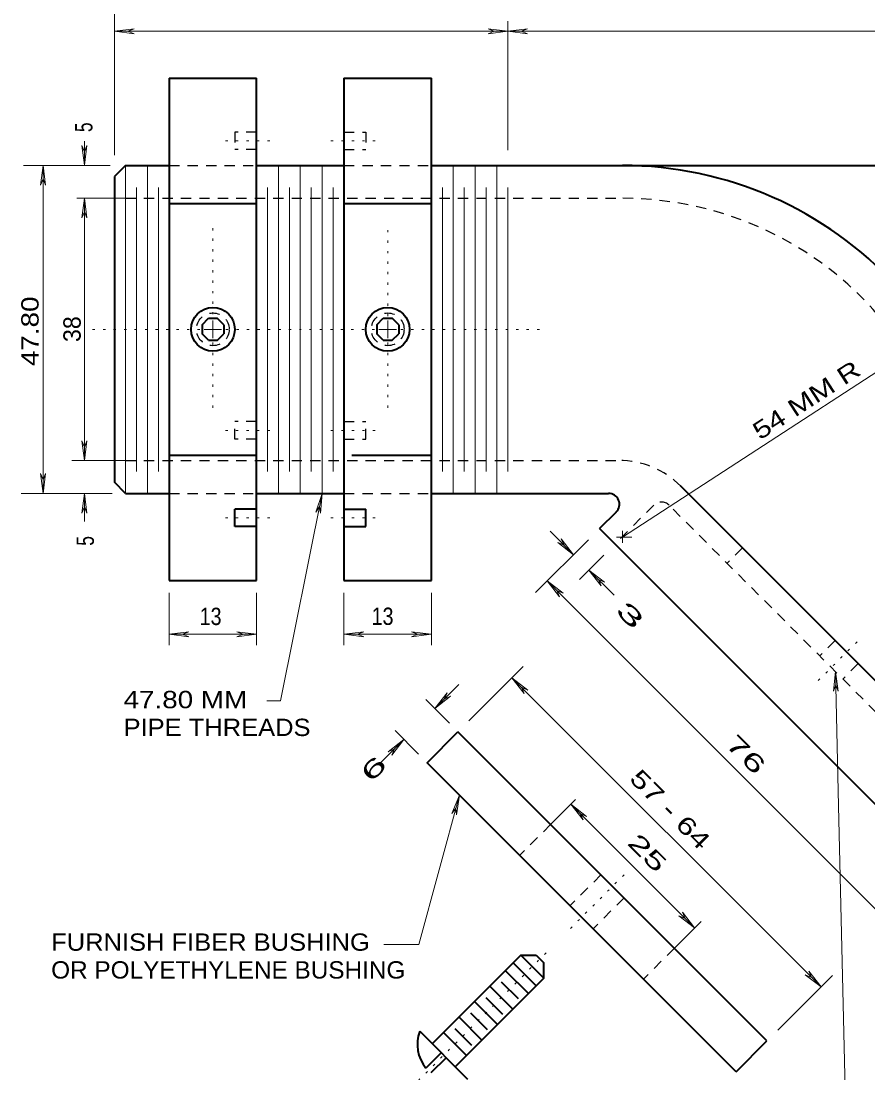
# Model space of a CAD drawing. Extents: x 312583 to 312854, y 144419 to 144597.
# Drawn here: x 312617.84 to 312654.99, y 144442.87 to 144489 of the extents above; entities that cross this region are included whole.
import ezdxf

# ---------------------------------------------------------------- set-up
doc = ezdxf.new("R2010")
doc.units = 0
doc.header["$LTSCALE"] = 0.3
doc.linetypes.add('DOTTED', pattern=[1.5, 0.3, -1.2])
doc.linetypes.add('SHORT_DASHED', pattern=[2.7, 1.5, -1.2])
doc.layers.add('1', color=7, linetype='Continuous', lineweight=40)
doc.layers.add('2', color=7, linetype='Continuous', lineweight=13)

msp = doc.modelspace()

# ---------------------------------------------------------------- linework, layer by layer
at = {"layer": '1'}
for p, q in [((312624.3434, 144486.4942), (312628.1767, 144486.4942)), ((312624.3434, 144486.4942), (312624.3434, 144464.4602)), ((312628.1767, 144464.4602), (312628.1767, 144486.4942)), ((312632.01, 144486.4942), (312635.8434, 144486.4942)), ((312632.01, 144486.4942), (312632.01, 144464.4602)), ((312635.8434, 144464.4602), (312635.8434, 144486.4942)), ((312622.4267, 144482.6609), (312621.9437, 144482.1779)), ((312622.4267, 144482.6609), (312624.3434, 144482.6609)), ((312628.1767, 144482.6609), (312632.01, 144482.6609)), ((312635.8434, 144482.6609), (312667.9437, 144482.6609)), ((312621.9437, 144482.1779), (312621.9437, 144468.7689)), ((312624.3434, 144480.9896), (312628.1767, 144480.9896)), ((312632.01, 144480.9896), (312635.8434, 144480.9896)), ((312625.7847, 144475.6766), (312626.0684, 144475.9602)), ((312626.0684, 144475.9602), (312626.4517, 144475.9602)), ((312626.743, 144475.6689), (312626.4517, 144475.9602)), ((312633.4514, 144475.6766), (312633.735, 144475.9602)), ((312633.735, 144475.9602), (312634.1184, 144475.9602)), ((312634.4097, 144475.6689), (312634.1184, 144475.9602)), ((312625.7847, 144475.6766), (312625.7847, 144475.2779)), ((312626.4594, 144475.0019), (312626.743, 144475.2856)), ((312626.743, 144475.6689), (312626.743, 144475.2856)), ((312633.4514, 144475.6766), (312633.4514, 144475.2779)), ((312634.126, 144475.0019), (312634.4097, 144475.2856)), ((312634.4097, 144475.6689), (312634.4097, 144475.2856)), ((312626.0607, 144475.0019), (312625.7847, 144475.2779)), ((312626.0607, 144475.0019), (312626.4594, 144475.0019)), ((312633.7274, 144475.0019), (312633.4514, 144475.2779)), ((312633.7274, 144475.0019), (312634.126, 144475.0019)), ((312624.3434, 144469.9649), (312628.1767, 144469.9649)), ((312632.355, 144469.9649), (312635.8434, 144469.9649)), ((312622.4267, 144468.2859), (312621.9437, 144468.7689)), ((312662.1937, 144453.1902), (312646.776, 144468.6079)), ((312622.4267, 144468.2859), (312624.3434, 144468.2859)), ((312628.1767, 144468.2859), (312632.01, 144468.2859)), ((312635.8434, 144468.2859), (312643.6097, 144468.2859)), ((312628.1767, 144467.5959), (312627.2184, 144467.5959)), ((312627.2184, 144466.8292), (312627.2184, 144467.5959)), ((312632.01, 144467.5959), (312632.9684, 144467.5959)), ((312632.9684, 144466.8292), (312632.9684, 144467.5959)), ((312643.947, 144467.4656), (312643.2187, 144466.7372)), ((312628.1767, 144466.8292), (312627.2184, 144466.8292)), ((312632.01, 144466.8292), (312632.9684, 144466.8292)), ((312659.4797, 144450.4762), (312643.2187, 144466.7372)), ((312624.3434, 144464.4602), (312628.1767, 144464.4602)), ((312632.01, 144464.4602), (312635.8434, 144464.4602)), ((312650.5634, 144444.2739), (312637.0087, 144457.8286)), ((312639.761, 144448.0382), (312635.874, 144444.1512)), ((312639.4237, 144447.7009), (312640.4357, 144446.6889)), ((312639.761, 144448.0382), (312640.4357, 144448.0382)), ((312640.4357, 144448.0382), (312640.773, 144447.7009)), ((312639.0864, 144447.3636), (312640.0984, 144446.3516)), ((312639.5847, 144447.5399), (312640.3207, 144446.8039)), ((312640.773, 144447.0262), (312636.886, 144443.1392)), ((312638.91, 144446.8652), (312639.646, 144446.1292)), ((312638.404, 144446.6812), (312639.416, 144445.6692)), ((312637.7294, 144446.0066), (312638.7414, 144444.9946)), ((312638.2277, 144446.1829), (312638.9637, 144445.4469)), ((312637.047, 144445.3242), (312638.059, 144444.3122)), ((312637.553, 144445.5082), (312638.289, 144444.7722)), ((312635.3297, 144444.6956), (312637.4304, 144442.5949)), ((312636.3724, 144444.6496), (312637.3844, 144443.6376)), ((312636.8707, 144444.8259), (312637.6067, 144444.0899)), ((312649.2064, 144442.9169), (312650.5634, 144444.2739)), ((312636.2727, 144443.7526), (312635.6057, 144443.0856)), ((312636.4874, 144443.5379), (312635.8204, 144442.8709))]:
    msp.add_line(p, q, dxfattribs=at)
at = {"layer": '1', "linetype": 'SHORT_DASHED', "lineweight": 25}
for p, q in [((312627.2184, 144484.1252), (312627.2184, 144483.3586)), ((312628.1767, 144484.1252), (312627.2184, 144484.1252)), ((312632.01, 144484.1252), (312632.9684, 144484.1252)), ((312632.9684, 144484.1252), (312632.9684, 144483.3586)), ((312628.1767, 144483.3586), (312627.2184, 144483.3586)), ((312632.01, 144483.3586), (312632.9684, 144483.3586)), ((312624.3434, 144482.6609), (312628.1767, 144482.6609)), ((312632.01, 144482.6609), (312635.8434, 144482.6609)), ((312622.4267, 144481.2272), (312644.223, 144481.2272)), ((312628.1767, 144471.4292), (312627.2184, 144471.4292)), ((312627.2184, 144470.6626), (312627.2184, 144471.4292)), ((312632.01, 144471.4292), (312632.9684, 144471.4292)), ((312632.9684, 144470.6626), (312632.9684, 144471.4292)), ((312628.1767, 144470.6626), (312627.2184, 144470.6626)), ((312632.01, 144470.6626), (312632.9684, 144470.6626)), ((312622.4267, 144469.7272), (312644.0697, 144469.7272)), ((312624.3434, 144468.2859), (312628.1767, 144468.2859)), ((312632.01, 144468.2859), (312635.8434, 144468.2859)), ((312645.5954, 144467.7646), (312643.8934, 144466.0626)), ((312660.507, 144453.5276), (312646.27, 144467.7646)), ((312649.49, 144465.8939), (312648.8154, 144465.2192)), ((312653.5534, 144461.8306), (312652.8787, 144461.1559)), ((312654.5654, 144460.8186), (312653.8907, 144460.1439)), ((312641.072, 144453.7652), (312639.715, 144452.4082)), ((312643.28, 144451.5572), (312641.923, 144450.2002)), ((312644.292, 144450.5452), (312642.935, 144449.1882)), ((312646.5, 144448.3372), (312645.143, 144446.9802))]:
    msp.add_line(p, q, dxfattribs=at)
at = {"layer": '1', "linetype": 'DOTTED', "lineweight": 13}
for p, q in [((312628.7517, 144483.7419), (312626.6357, 144483.7419)), ((312631.435, 144483.7419), (312633.551, 144483.7419)), ((312628.7517, 144471.0459), (312626.6357, 144471.0459)), ((312631.435, 144471.0459), (312633.551, 144471.0459)), ((312628.7517, 144467.2126), (312626.6357, 144467.2126)), ((312631.435, 144467.2126), (312633.551, 144467.2126)), ((312654.5117, 144461.7769), (312652.779, 144460.0442)), ((312644.292, 144451.5572), (312641.923, 144449.1882)), ((312640.8727, 144448.1379), (312635.1994, 144442.4646))]:
    msp.add_line(p, q, dxfattribs=at)
at = {"layer": '1', "lineweight": 13}
for p, q in [((312622.4267, 144482.6609), (312622.4267, 144468.2859)), ((312623.385, 144482.6609), (312623.385, 144468.2859)), ((312629.135, 144482.6609), (312629.135, 144468.2859)), ((312630.0934, 144482.6609), (312630.0934, 144468.2859)), ((312631.0517, 144482.6609), (312631.0517, 144468.2859)), ((312636.8017, 144482.6609), (312636.8017, 144468.2859)), ((312637.76, 144482.6609), (312637.76, 144468.2859)), ((312638.7184, 144482.6609), (312638.7184, 144468.2859)), ((312622.9097, 144481.7026), (312622.9097, 144469.2442)), ((312623.868, 144481.7026), (312623.868, 144469.2442)), ((312628.6597, 144481.7026), (312628.6597, 144469.2442)), ((312629.618, 144481.7026), (312629.618, 144469.2442)), ((312630.5764, 144481.7026), (312630.5764, 144469.2442)), ((312631.5347, 144481.7026), (312631.5347, 144469.2442)), ((312636.3264, 144481.7026), (312636.3264, 144469.2442)), ((312637.2847, 144481.7026), (312637.2847, 144469.2442)), ((312638.243, 144481.7026), (312638.243, 144469.2442)), ((312639.1937, 144481.7026), (312639.1937, 144469.2442))]:
    msp.add_line(p, q, dxfattribs=at)
at = {"layer": '1'}
for points in [[(312649.2064, 144442.9169), (312635.6517, 144456.4716), (312637.0087, 144457.8286)], [(312639.761, 144448.0382), (312640.773, 144447.0262), (312640.773, 144447.7009)]]:
    msp.add_lwpolyline(points, dxfattribs=at)
for centre in [(312626.26, 144475.4772), (312633.9267, 144475.4772)]:
    msp.add_circle(centre, 0.9583, dxfattribs=at)
at = {"layer": '1', "linetype": 'SHORT_DASHED', "lineweight": 25}
for centre in [(312626.26, 144475.4772), (312633.9267, 144475.4772)]:
    msp.add_circle(centre, 0.7188, dxfattribs=at)
at = {"layer": '1'}
for centre, radius, start, end in [((312644.223, 144466.3692), 16.2917, 354.95144, 90), ((312643.6106, 144467.8067), 0.4792, 315, 90), ((312636.8603, 144444.1255), 1.6333, 159.57183, 219.65516)]:
    msp.add_arc(centre, radius, start, end, dxfattribs=at)
at = {"layer": '1', "linetype": 'SHORT_DASHED', "lineweight": 25}
for centre, radius, start, end in [((312644.223, 144466.3692), 14.8542, 354.46141, 90), ((312644.0689, 144465.8939), 3.8333, 45, 90), ((312645.9327, 144467.4243), 0.4792, 45, 135)]:
    msp.add_arc(centre, radius, start, end, dxfattribs=at)
at = {"layer": '2'}
for p, q in [((312621.9437, 144483.1132), (312621.9437, 144491.9452)), ((312639.1937, 144483.3356), (312639.1937, 144488.9859)), ((312621.9437, 144488.5489), (312622.81, 144488.6562)), ((312621.9437, 144488.5489), (312622.81, 144488.4416)), ((312622.81, 144488.6562), (312622.534, 144488.5489)), ((312622.81, 144488.4416), (312622.534, 144488.5489)), ((312638.3274, 144488.6562), (312638.6034, 144488.5489)), ((312639.1937, 144488.5489), (312638.3274, 144488.6562)), ((312638.3274, 144488.4416), (312638.6034, 144488.5489)), ((312639.1937, 144488.5489), (312638.3274, 144488.4416)), ((312639.1937, 144488.5489), (312640.06, 144488.6562)), ((312639.1937, 144488.5489), (312640.06, 144488.4416)), ((312640.06, 144488.6562), (312639.784, 144488.5489)), ((312640.06, 144488.4416), (312639.784, 144488.5489)), ((312620.6222, 144482.6762), (312620.6222, 144483.7342)), ((312620.5149, 144483.5426), (312620.6222, 144483.2666)), ((312620.6222, 144482.6762), (312620.5149, 144483.5426)), ((312620.7295, 144483.5426), (312620.6222, 144483.2666)), ((312620.6222, 144482.6762), (312620.7295, 144483.5426)), ((312621.752, 144482.6609), (312617.9586, 144482.6609)), ((312618.8124, 144482.6609), (312618.7051, 144481.7946)), ((312618.8124, 144468.2859), (312618.8124, 144482.6609)), ((312618.8124, 144482.6609), (312618.9198, 144481.7946)), ((312618.7051, 144481.7946), (312618.8124, 144482.0706)), ((312618.9198, 144481.7946), (312618.8124, 144482.0706)), ((312622.4267, 144481.2272), (312620.2913, 144481.2272)), ((312620.6222, 144481.2272), (312620.5149, 144480.3609)), ((312620.6222, 144481.2272), (312620.7295, 144480.3609)), ((312620.6222, 144469.7272), (312620.6222, 144481.2272)), ((312620.5149, 144480.3609), (312620.6222, 144480.6369)), ((312620.7295, 144480.3609), (312620.6222, 144480.6369)), ((312626.26, 144475.4772), (312626.26, 144475.8606)), ((312633.9267, 144475.4772), (312633.9267, 144475.8606)), ((312626.26, 144475.4772), (312625.8767, 144475.4772)), ((312626.26, 144475.4772), (312626.6434, 144475.4772)), ((312626.26, 144475.4772), (312626.26, 144475.0939)), ((312633.9267, 144475.4772), (312633.5434, 144475.4772)), ((312633.9267, 144475.4772), (312634.31, 144475.4772)), ((312633.9267, 144475.4772), (312633.9267, 144475.0939)), ((312644.223, 144466.3692), (312657.885, 144475.2396)), ((312620.5149, 144470.5936), (312620.6222, 144470.3176)), ((312620.6222, 144469.7272), (312620.5149, 144470.5936)), ((312620.7295, 144470.5936), (312620.6222, 144470.3176)), ((312620.6222, 144469.7272), (312620.7295, 144470.5936)), ((312622.4267, 144469.7272), (312620.0787, 144469.7272)), ((312618.7051, 144469.1522), (312618.8124, 144468.8762)), ((312618.8124, 144468.2859), (312618.7051, 144469.1522)), ((312618.9198, 144469.1522), (312618.8124, 144468.8762)), ((312618.8124, 144468.2859), (312618.9198, 144469.1522)), ((312621.8364, 144468.2859), (312617.8523, 144468.2859)), ((312620.6222, 144468.2859), (312620.5149, 144467.4196)), ((312620.6222, 144467.0439), (312620.6222, 144468.2859)), ((312620.6222, 144468.2859), (312620.7295, 144467.4196)), ((312631.0517, 144468.2859), (312630.7757, 144467.4579)), ((312631.0517, 144468.2859), (312630.9827, 144467.4196)), ((312620.5149, 144467.4196), (312620.6222, 144467.6956)), ((312620.7295, 144467.4196), (312620.6222, 144467.6956)), ((312630.7757, 144467.4579), (312630.9367, 144467.7109)), ((312630.9827, 144467.4196), (312630.9367, 144467.7109)), ((312642.0764, 144465.5949), (312641.049, 144466.6222)), ((312644.223, 144466.1086), (312644.223, 144466.6452)), ((312642.728, 144466.2466), (312640.4127, 144463.9312)), ((312641.3864, 144466.1316), (312641.6624, 144466.0089)), ((312642.0764, 144465.5949), (312641.3864, 144466.1316)), ((312641.5397, 144466.2849), (312641.6624, 144466.0089)), ((312642.0764, 144465.5949), (312641.5397, 144466.2849)), ((312643.9624, 144466.3692), (312644.6294, 144466.3692)), ((312643.4027, 144465.5719), (312642.337, 144464.5062)), ((312643.855, 144463.8239), (312642.751, 144464.9202)), ((312642.751, 144464.9202), (312643.2877, 144464.2302)), ((312642.751, 144464.9202), (312643.441, 144464.3836)), ((312657.1874, 144448.1839), (312640.9264, 144464.4449)), ((312640.9264, 144464.4449), (312641.463, 144463.7549)), ((312640.9264, 144464.4449), (312641.6164, 144463.9082)), ((312643.2877, 144464.2302), (312643.1727, 144464.5062)), ((312643.441, 144464.3836), (312643.1727, 144464.5062)), ((312624.3434, 144463.9159), (312624.3434, 144461.6312)), ((312628.1767, 144463.9159), (312628.1767, 144461.6312)), ((312632.01, 144463.9159), (312632.01, 144461.6312)), ((312635.8434, 144463.9159), (312635.8434, 144461.6312)), ((312641.463, 144463.7549), (312641.3404, 144464.0309)), ((312641.6164, 144463.9082), (312641.3404, 144464.0309)), ((312624.3434, 144462.1066), (312625.2097, 144462.2139)), ((312624.3434, 144462.1066), (312628.1767, 144462.1066)), ((312624.3434, 144462.1066), (312625.2097, 144461.9992)), ((312625.2097, 144462.2139), (312624.9337, 144462.1066)), ((312625.2097, 144461.9992), (312624.9337, 144462.1066)), ((312627.3104, 144462.2139), (312627.5864, 144462.1066)), ((312628.1767, 144462.1066), (312627.3104, 144462.2139)), ((312627.3104, 144461.9992), (312627.5864, 144462.1066)), ((312628.1767, 144462.1066), (312627.3104, 144461.9992)), ((312632.01, 144462.1066), (312632.8764, 144462.2139)), ((312632.01, 144462.1066), (312635.8434, 144462.1066)), ((312632.01, 144462.1066), (312632.8764, 144461.9992)), ((312632.8764, 144462.2139), (312632.6004, 144462.1066)), ((312632.8764, 144461.9992), (312632.6004, 144462.1066)), ((312634.977, 144462.2139), (312635.253, 144462.1066)), ((312635.8434, 144462.1066), (312634.977, 144462.2139)), ((312634.977, 144461.9992), (312635.253, 144462.1066)), ((312635.8434, 144462.1066), (312634.977, 144461.9992)), ((312637.484, 144458.3039), (312639.876, 144460.6959)), ((312639.3777, 144460.1976), (312652.9324, 144446.6429)), ((312639.3777, 144460.1976), (312639.9144, 144459.5076)), ((312639.3777, 144460.1976), (312640.0677, 144459.6609)), ((312653.561, 144460.4736), (312653.4767, 144459.6072)), ((312653.561, 144460.4736), (312653.6914, 144459.6072)), ((312653.561, 144460.4736), (312653.699, 144454.5856)), ((312635.9967, 144458.8482), (312637.047, 144459.8986)), ((312639.9144, 144459.5076), (312639.7917, 144459.7836)), ((312640.0677, 144459.6609), (312639.7917, 144459.7836)), ((312653.4767, 144459.6072), (312653.5764, 144459.8832)), ((312653.6914, 144459.6072), (312653.5764, 144459.8832)), ((312636.6407, 144458.2042), (312635.6057, 144459.2392)), ((312635.9967, 144458.8482), (312636.5334, 144459.5382)), ((312635.9967, 144458.8482), (312636.6867, 144459.3849)), ((312636.5334, 144459.5382), (312636.4107, 144459.2622)), ((312636.6867, 144459.3849), (312636.4107, 144459.2622)), ((312635.276, 144456.8472), (312634.2487, 144457.8822)), ((312633.5434, 144456.3949), (312634.6397, 144457.4912)), ((312634.6397, 144457.4912), (312633.9497, 144456.9546)), ((312634.6397, 144457.4912), (312634.103, 144456.8012)), ((312633.9497, 144456.9546), (312634.2257, 144457.0772)), ((312634.103, 144456.8012), (312634.2257, 144457.0772)), ((312637.07, 144455.0532), (312636.7404, 144454.2482)), ((312637.07, 144455.0532), (312636.9474, 144454.1869)), ((312641.072, 144453.7652), (312642.1607, 144454.8539)), ((312641.9614, 144454.6546), (312647.3894, 144449.2266)), ((312641.9614, 144454.6546), (312642.498, 144453.9646)), ((312641.9614, 144454.6546), (312642.6514, 144454.1179)), ((312653.6971, 144454.5856), (312653.9904, 144442.1502)), ((312636.7404, 144454.2482), (312636.9167, 144454.4859)), ((312636.9474, 144454.1869), (312636.9167, 144454.4859)), ((312642.498, 144453.9646), (312642.3754, 144454.2406)), ((312642.6514, 144454.1179), (312642.3754, 144454.2406)), ((312646.8527, 144449.9166), (312646.9754, 144449.6406)), ((312647.3894, 144449.2266), (312646.8527, 144449.9166)), ((312646.5, 144448.3372), (312647.673, 144449.5102)), ((312646.6994, 144449.7632), (312646.9754, 144449.6406)), ((312647.3894, 144449.2266), (312646.6994, 144449.7632)), ((312652.2424, 144447.1796), (312652.5184, 144447.0569)), ((312652.9324, 144446.6429), (312652.2424, 144447.1796)), ((312652.3957, 144447.3329), (312652.5184, 144447.0569)), ((312652.9324, 144446.6429), (312652.3957, 144447.3329)), ((312651.0387, 144444.7492), (312653.4307, 144447.1412))]:
    msp.add_line(p, q, dxfattribs=at)
at = {"layer": '2', "linetype": 'DOTTED'}
for p, q in [((312626.26, 144479.9162), (312626.26, 144474.9022)), ((312633.9267, 144476.0522), (312633.9267, 144479.9162)), ((312625.685, 144475.4772), (312620.6557, 144475.4772)), ((312626.835, 144475.4772), (312630.078, 144475.4772)), ((312633.3517, 144475.4772), (312630.078, 144475.4772)), ((312634.5017, 144475.4772), (312640.6274, 144475.4772)), ((312626.26, 144474.9022), (312626.26, 144471.7129)), ((312633.9267, 144474.9022), (312633.9267, 144471.7129))]:
    msp.add_line(p, q, dxfattribs=at)
at = {"layer": '2'}
for points in [[(312621.9437, 144488.5489), (312639.1937, 144488.5489), (312666.027, 144488.5489), (312673.6937, 144488.5489)], [(312631.0517, 144468.2859), (312629.2194, 144459.1856), (312628.6214, 144459.1856)], [(312637.07, 144455.0532), (312635.2914, 144448.5059), (312633.758, 144448.5059)]]:
    msp.add_lwpolyline(points, dxfattribs=at)

# ---------------------------------------------------------------- texts
for s, rotation, width, p in [('5', 90, 0.75, (312620.9763, 144484.127)), ('47.80', 90, 1.2, (312618.6163, 144473.8663)), ('54 MM R', 32.994, 1.3, (312650.2512, 144470.6022)), ('5', 90, 0.75, (312621.0413, 144465.9889)), ('3', 315, 2.1, (312643.8746, 144463.1)), ('76', 315, 1.7, (312648.6925, 144457.2483)), ('6 ', 45, 1.9, (312633.1963, 144455.5712)), ('57 - 64 ', 315, 1.4, (312644.4839, 144455.7252)), ('25', 315, 1.65, (312644.396, 144452.9145))]:
    msp.add_text(s, height=0.76, rotation=rotation, dxfattribs=dict(at, width=width)).set_placement(p)
msp.add_text('38', height=0.76, rotation=90, dxfattribs=at).set_placement((312620.4616, 144474.9212))
for s, width, p in [('13', 0.85, (312625.6783, 144462.51)), ('13', 0.85, (312633.2214, 144462.5159)), ('47.80 MM', 1.2, (312622.3426, 144458.8636)), ('PIPE THREADS', 1.1, (312622.3426, 144457.6436)), ('FURNISH FIBER BUSHING', 1.1, (312619.167, 144448.2289)), ('OR POLYETHYLENE BUSHING', 1.05, (312619.167, 144447.0089))]:
    msp.add_text(s, height=0.76, dxfattribs=dict(at, width=width)).set_placement(p)

doc.saveas('drawing.dxf')
